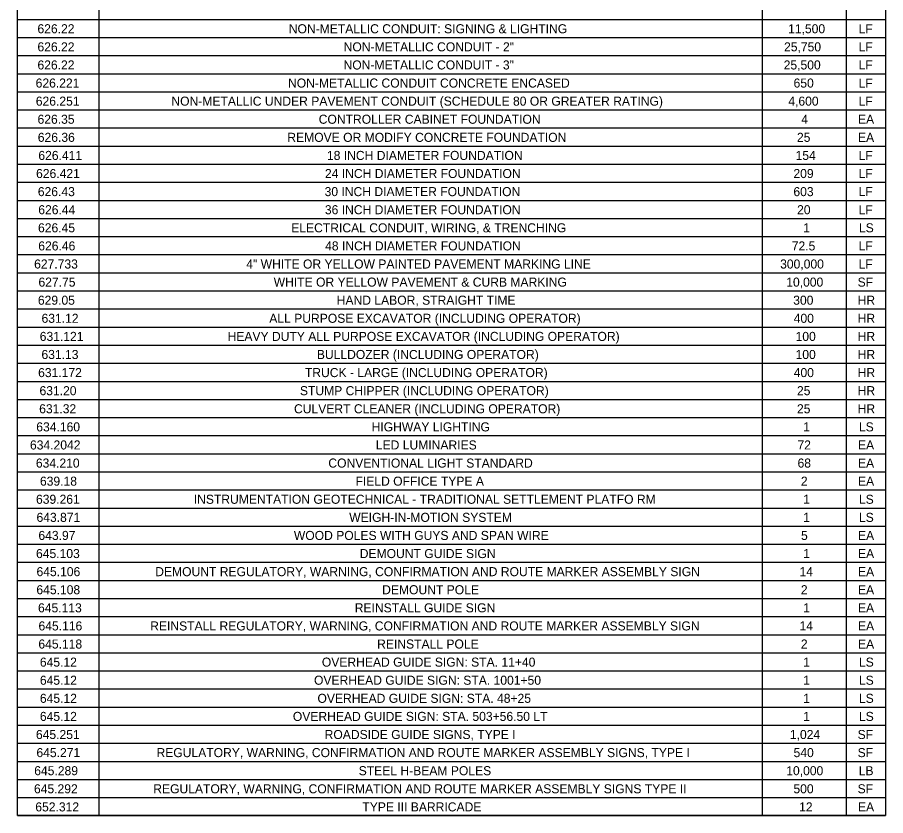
# Model space of a CAD drawing. Extents: x -18.7 to 5.6, y -2.7 to 5.1.
# Drawn here: x -6.23 to -5.286, y -0.314 to 0.554 of the extents above; entities that cross this region are included whole.
import ezdxf

# ---------------------------------------------------------------- set-up
doc = ezdxf.new("R2010")
doc.units = 0
doc.layers.add('ANNOTATION', color=7, linetype='Continuous')
doc.layers.add('BORDER', color=7, linetype='Continuous')

msp = doc.modelspace()

# ---------------------------------------------------------------- linework, layer by layer
at = {"layer": 'BORDER'}
for p, q in [((-6.14178, 1.39863), (-6.14178, -0.31405)), ((-5.42047, 1.39863), (-5.42047, -0.31405)), ((-5.32908, 1.39863), (-5.32908, -0.31405)), ((-6.23036, 0.55213), (-5.28608, 0.55213)), ((-6.23036, 0.53245), (-5.28608, 0.53245)), ((-6.23036, 0.51276), (-5.28608, 0.51276)), ((-6.23036, 0.49308), (-5.28608, 0.49308)), ((-6.23036, 0.47339), (-5.28608, 0.47339)), ((-6.23036, 0.4537), (-5.28608, 0.4537)), ((-6.23036, 0.43402), (-5.28608, 0.43402)), ((-6.23036, 0.41433), (-5.28608, 0.41433)), ((-6.23036, 0.39465), (-5.28608, 0.39465)), ((-6.23036, 0.37496), (-5.28608, 0.37496)), ((-6.23036, 0.35527), (-5.28608, 0.35527)), ((-6.23036, 0.33559), (-5.28608, 0.33559)), ((-6.23036, 0.3159), (-5.28608, 0.3159)), ((-6.23036, 0.29622), (-5.28608, 0.29622)), ((-6.23036, 0.27653), (-5.28608, 0.27653)), ((-6.23036, 0.25684), (-5.28608, 0.25684)), ((-6.23036, 0.23716), (-5.28608, 0.23716)), ((-6.23036, 0.21747), (-5.28608, 0.21747)), ((-6.23036, 0.19779), (-5.28608, 0.19779)), ((-6.23036, 0.1781), (-5.28608, 0.1781)), ((-6.23036, 0.15841), (-5.28608, 0.15841)), ((-6.23036, 0.13873), (-5.28608, 0.13873)), ((-6.23036, 0.11904), (-5.28608, 0.11904)), ((-6.23036, 0.09936), (-5.28608, 0.09936)), ((-6.23036, 0.07967), (-5.28608, 0.07967)), ((-6.23036, 0.05998), (-5.28608, 0.05998)), ((-6.23036, 0.0403), (-5.28608, 0.0403)), ((-6.23036, 0.02061), (-5.28608, 0.02061)), ((-6.23036, 0.00093), (-5.28608, 0.00093)), ((-6.23036, -0.01876), (-5.28608, -0.01876)), ((-6.23036, -0.03845), (-5.28608, -0.03845)), ((-6.23036, -0.05813), (-5.28608, -0.05813)), ((-6.23036, -0.07782), (-5.28608, -0.07782)), ((-6.23036, -0.0975), (-5.28608, -0.0975)), ((-6.23036, -0.11719), (-5.28608, -0.11719)), ((-6.23036, -0.13688), (-5.28608, -0.13688)), ((-6.23036, -0.15656), (-5.28608, -0.15656)), ((-6.23036, -0.17625), (-5.28608, -0.17625)), ((-6.23036, -0.19593), (-5.28608, -0.19593)), ((-6.23036, -0.21562), (-5.28608, -0.21562)), ((-6.23036, -0.23531), (-5.28608, -0.23531)), ((-6.23036, -0.25499), (-5.28608, -0.25499)), ((-6.23036, -0.27468), (-5.28608, -0.27468)), ((-6.23036, -0.29436), (-5.28608, -0.29436)), ((-6.23036, -0.31405), (-5.28608, -0.31405))]:
    msp.add_line(p, q, dxfattribs=at)
msp.add_lwpolyline([(-6.23036, 1.41832), (-5.28608, 1.41832), (-5.28608, -0.31405), (-6.23036, -0.31405)], close=True, dxfattribs=at)

# ---------------------------------------------------------------- texts
at = {"layer": 'ANNOTATION'}
for s, height, p in [('626.22', 0.009843, (-6.2085, 0.53704)), ('NON-METALLIC CONDUIT: SIGNING & LIGHTING', 0.009843, (-5.93518, 0.53704)), ('11,500', 0.009843, (-5.39215, 0.53704)), ('LF', 0.009843, (-5.31553, 0.53704)), ('626.22', 0.009843, (-6.2085, 0.51736)), ('NON-METALLIC CONDUIT - 2"', 0.009843, (-5.87554, 0.51736)), ('25,750', 0.009843, (-5.39657, 0.51736)), ('LF', 0.009843, (-5.31553, 0.51736)), ('626.22', 0.009843, (-6.2085, 0.49767)), ('NON-METALLIC CONDUIT - 3"', 0.009843, (-5.87562, 0.49767)), ('25,500', 0.009843, (-5.39696, 0.49767)), ('LF', 0.009843, (-5.31553, 0.49767)), ('626.221', 0.009843, (-6.21047, 0.47799)), ('NON-METALLIC CONDUIT CONCRETE ENCASED', 0.009843, (-5.93602, 0.47799)), ('650', 0.009843, (-5.38619, 0.47799)), ('LF', 0.009843, (-5.31553, 0.47799)), ('626.251', 0.009843, (-6.21032, 0.4583)), ('NON-METALLIC UNDER PAVEMENT CONDUIT (SCHEDULE 80 OR GREATER RATING)', 0.009843, (-6.06286, 0.4583)), ('4,600', 0.009843, (-5.39192, 0.4583)), ('LF', 0.009843, (-5.31553, 0.4583)), ('626.35', 0.009843, (-6.20842, 0.43861)), ('CONTROLLER CABINET FOUNDATION', 0.009843, (-5.90264, 0.43861)), ('4', 0.00984, (-5.37782, 0.43861)), ('EA', 0.009843, (-5.31615, 0.43861)), ('626.36', 0.009843, (-6.20815, 0.41893)), ('REMOVE OR MODIFY CONCRETE FOUNDATION', 0.009843, (-5.93677, 0.41893)), ('25', 0.009843, (-5.38251, 0.41893)), ('EA', 0.009843, (-5.31615, 0.41893)), ('626.411', 0.009843, (-6.20753, 0.39924)), ('18 INCH DIAMETER FOUNDATION', 0.009843, (-5.89367, 0.39924)), ('154', 0.009843, (-5.38402, 0.39924)), ('LF', 0.009843, (-5.31553, 0.39924)), ('626.421', 0.009843, (-6.21001, 0.37956)), ('24 INCH DIAMETER FOUNDATION', 0.009843, (-5.89584, 0.37956)), ('209', 0.009843, (-5.38635, 0.37956)), ('LF', 0.009843, (-5.31553, 0.37956)), ('626.43', 0.009843, (-6.20811, 0.35987)), ('30 INCH DIAMETER FOUNDATION', 0.009843, (-5.89622, 0.35987)), ('603', 0.009843, (-5.38638, 0.35987)), ('LF', 0.009843, (-5.31553, 0.35987)), ('626.44', 0.009843, (-6.2076, 0.34018)), ('36 INCH DIAMETER FOUNDATION', 0.009843, (-5.89591, 0.34018)), ('20', 0.009843, (-5.38239, 0.34018)), ('LF', 0.009843, (-5.31553, 0.34018)), ('626.45', 0.009843, (-6.20788, 0.3205)), ('ELECTRICAL CONDUIT, WIRING, & TRENCHING', 0.009843, (-5.93252, 0.3205)), ('1', 0.00984, (-5.37581, 0.3205)), ('LS', 0.009843, (-5.31511, 0.3205)), ('626.46', 0.009843, (-6.2076, 0.30081)), ('48 INCH DIAMETER FOUNDATION', 0.009843, (-5.89568, 0.30081)), ('72.5', 0.009843, (-5.38816, 0.30081)), ('LF', 0.009843, (-5.31553, 0.30081)), ('627.733', 0.009843, (-6.21214, 0.28113)), ('4" WHITE OR YELLOW PAINTED PAVEMENT MARKING LINE', 0.009843, (-5.98142, 0.28113)), ('300,000', 0.009843, (-5.40083, 0.28113)), ('LF', 0.009843, (-5.31553, 0.28113)), ('627.75', 0.009843, (-6.20741, 0.26144)), ('WHITE OR YELLOW PAVEMENT & CURB MARKING', 0.009843, (-5.9516, 0.26144)), ('10,000', 0.009843, (-5.39416, 0.26144)), ('SF', 0.009843, (-5.31654, 0.26144)), ('629.05', 0.009843, (-6.20803, 0.24175)), ('HAND LABOR, STRAIGHT TIME', 0.009843, (-5.88307, 0.24175)), ('300', 0.009843, (-5.38658, 0.24175)), ('HR', 0.009843, (-5.31652, 0.24175)), ('631.12', 0.009843, (-6.20408, 0.22207)), ('ALL PURPOSE EXCAVATOR (INCLUDING OPERATOR)', 0.009843, (-5.95639, 0.22207)), ('400', 0.009843, (-5.38603, 0.22207)), ('HR', 0.009843, (-5.31652, 0.22207)), ('631.121', 0.009843, (-6.20605, 0.20238)), ('HEAVY DUTY ALL PURPOSE EXCAVATOR (INCLUDING OPERATOR)', 0.009843, (-6.00176, 0.20238)), ('100', 0.009843, (-5.38402, 0.20238)), ('HR', 0.009843, (-5.31652, 0.20238)), ('631.13', 0.009843, (-6.20416, 0.1827)), ('BULLDOZER (INCLUDING OPERATOR)', 0.009843, (-5.90467, 0.1827)), ('100', 0.009843, (-5.38402, 0.1827)), ('HR', 0.009843, (-5.31652, 0.1827)), ('631.172', 0.009843, (-6.2078, 0.16301)), ('TRUCK - LARGE (INCLUDING OPERATOR)', 0.009843, (-5.91764, 0.16301)), ('400', 0.009843, (-5.38603, 0.16301)), ('HR', 0.009843, (-5.31652, 0.16301)), ('631.20', 0.009843, (-6.20629, 0.14332)), ('STUMP CHIPPER (INCLUDING OPERATOR)', 0.009843, (-5.92308, 0.14332)), ('25', 0.009843, (-5.38251, 0.14332)), ('HR', 0.009843, (-5.31652, 0.14332)), ('631.32', 0.009843, (-6.20664, 0.12364)), ('CULVERT CLEANER (INCLUDING OPERATOR)', 0.009843, (-5.92949, 0.12364)), ('25', 0.009843, (-5.38251, 0.12364)), ('HR', 0.009843, (-5.31652, 0.12364)), ('634.160', 0.009843, (-6.20977, 0.10395)), ('HIGHWAY LIGHTING', 0.009843, (-5.84514, 0.10395)), ('1', 0.00984, (-5.37581, 0.10395)), ('LS', 0.009843, (-5.31511, 0.10395)), ('634.2042', 0.009843, (-6.21663, 0.08427)), ('LED LUMINARIES', 0.009843, (-5.84051, 0.08427)), ('72', 0.009843, (-5.38197, 0.08427)), ('EA', 0.009843, (-5.31615, 0.08427)), ('634.210', 0.009843, (-6.21024, 0.06458)), ('CONVENTIONAL LIGHT STANDARD', 0.009843, (-5.89215, 0.06458)), ('68', 0.009843, (-5.38189, 0.06458)), ('EA', 0.009843, (-5.31615, 0.06458)), ('639.18', 0.009843, (-6.20578, 0.04489)), ('FIELD OFFICE TYPE A', 0.009843, (-5.86261, 0.04489)), ('2', 0.00984, (-5.37825, 0.04489)), ('EA', 0.009843, (-5.31615, 0.04489)), ('639.261', 0.009843, (-6.21008, 0.02521)), ('INSTRUMENTATION GEOTECHNICAL - TRADITIONAL SETTLEMENT PLATFO RM', 0.009843, (-6.03853, 0.02521)), ('1', 0.00984, (-5.37581, 0.02521)), ('LS', 0.009843, (-5.31511, 0.02521)), ('643.871', 0.009843, (-6.20954, 0.00552)), ('WEIGH-IN-MOTION SYSTEM', 0.009843, (-5.86946, 0.00552)), ('1', 0.00984, (-5.37581, 0.00552)), ('LS', 0.009843, (-5.31511, 0.00552)), ('643.97', 0.009843, (-6.20745, -0.01416)), ('WOOD POLES WITH GUYS AND SPAN WIRE', 0.009843, (-5.92966, -0.01416)), ('5', 0.00984, (-5.37809, -0.01416)), ('EA', 0.009843, (-5.31615, -0.01416)), ('645.103', 0.009843, (-6.21005, -0.03385)), ('DEMOUNT GUIDE SIGN', 0.009843, (-5.858, -0.03385)), ('1', 0.00984, (-5.37581, -0.03385)), ('EA', 0.009843, (-5.31615, -0.03385)), ('645.106', 0.009843, (-6.20954, -0.05354)), ('DEMOUNT REGULATORY, WARNING, CONFIRMATION AND ROUTE MARKER ASSEMBLY SIGN', 0.009843, (-6.08044, -0.05354)), ('14', 0.009843, (-5.37976, -0.05354)), ('EA', 0.009843, (-5.31615, -0.05354)), ('645.108', 0.009843, (-6.20966, -0.07322)), ('DEMOUNT POLE', 0.009843, (-5.83364, -0.07322)), ('2', 0.00984, (-5.37825, -0.07322)), ('EA', 0.009843, (-5.31615, -0.07322)), ('645.113', 0.009843, (-6.20787, -0.09291)), ('REINSTALL GUIDE SIGN', 0.009843, (-5.86346, -0.09291)), ('1', 0.00984, (-5.37581, -0.09291)), ('EA', 0.009843, (-5.31615, -0.09291)), ('645.116', 0.009843, (-6.20737, -0.11259)), ('REINSTALL REGULATORY, WARNING, CONFIRMATION AND ROUTE MARKER ASSEMBLY SIGN', 0.009843, (-6.08591, -0.11259)), ('14', 0.009843, (-5.37976, -0.11259)), ('EA', 0.009843, (-5.31615, -0.11259)), ('645.118', 0.009843, (-6.20749, -0.13228)), ('REINSTALL POLE', 0.009843, (-5.8391, -0.13228)), ('2', 0.00984, (-5.37825, -0.13228)), ('EA', 0.009843, (-5.31615, -0.13228)), ('645.12', 0.009843, (-6.20586, -0.15197)), ('OVERHEAD GUIDE SIGN: STA. 11+40', 0.009843, (-5.89922, -0.15197)), ('1', 0.00984, (-5.37581, -0.15197)), ('LS', 0.009843, (-5.31511, -0.15197)), ('645.12', 0.009843, (-6.20586, -0.17165)), ('OVERHEAD GUIDE SIGN: STA. 1001+50', 0.009843, (-5.90774, -0.17165)), ('1', 0.00984, (-5.37581, -0.17165)), ('LS', 0.009843, (-5.31511, -0.17165)), ('645.12', 0.009843, (-6.20586, -0.19134)), ('OVERHEAD GUIDE SIGN: STA. 48+25', 0.009843, (-5.90399, -0.19134)), ('1', 0.00984, (-5.37581, -0.19134)), ('LS', 0.009843, (-5.31511, -0.19134)), ('645.12', 0.009843, (-6.20586, -0.21102)), ('OVERHEAD GUIDE SIGN: STA. 503+56.50 LT', 0.009843, (-5.93075, -0.21102)), ('1', 0.00984, (-5.37581, -0.21102)), ('LS', 0.009843, (-5.31511, -0.21102)), ('645.251', 0.009843, (-6.21016, -0.23071)), ('ROADSIDE GUIDE SIGNS, TYPE I', 0.009843, (-5.89621, -0.23071)), ('1,024', 0.009843, (-5.39021, -0.23071)), ('SF', 0.009843, (-5.31654, -0.23071)), ('645.271', 0.009843, (-6.20962, -0.2504)), ('REGULATORY, WARNING, CONFIRMATION AND ROUTE MARKER ASSEMBLY SIGNS, TYPE I', 0.009843, (-6.07904, -0.2504)), ('540', 0.009843, (-5.38619, -0.2504)), ('SF', 0.009843, (-5.31654, -0.2504)), ('645.289', 0.009843, (-6.21202, -0.27008)), ('STEEL H-BEAM POLES', 0.009843, (-5.85914, -0.27008)), ('10,000', 0.009843, (-5.39416, -0.27008)), ('LB', 0.009843, (-5.31534, -0.27008)), ('645.292', 0.009843, (-6.21229, -0.28977)), ('REGULATORY, WARNING, CONFIRMATION AND ROUTE MARKER ASSEMBLY SIGNS TYPE II', 0.009843, (-6.08259, -0.28977)), ('500', 0.009843, (-5.38635, -0.28977)), ('SF', 0.009843, (-5.31654, -0.28977)), ('652.312', 0.009843, (-6.21082, -0.30945)), ('TYPE III BARRICADE', 0.009843, (-5.85516, -0.30945)), ('12', 0.009843, (-5.38018, -0.30945)), ('EA', 0.009843, (-5.31615, -0.30945))]:
    msp.add_text(s, height=height, dxfattribs=at).set_placement(p)

doc.saveas('drawing.dxf')
